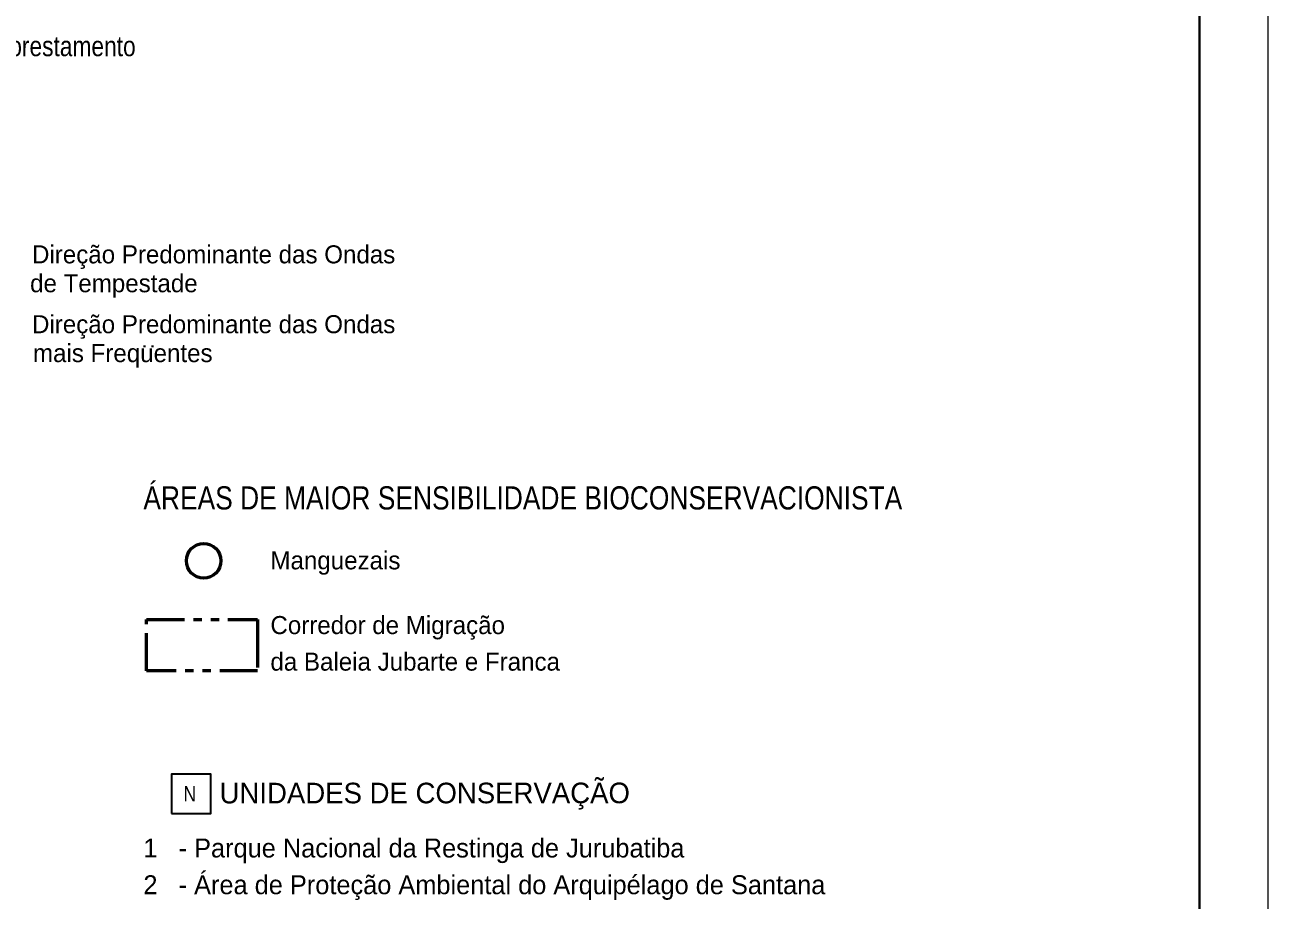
# Model space of a CAD drawing. Extents: x -6.3 to 58.7, y 19.8 to 60.6.
# Drawn here: x 43.55 to 58.68, y 39.84 to 50.49 of the extents above; entities that cross this region are included whole.
import ezdxf
from ezdxf.enums import TextEntityAlignment as Align

# ---------------------------------------------------------------- set-up
doc = ezdxf.new("R2010")
doc.units = 0
doc.header["$LTSCALE"] = 0.092
doc.linetypes.add('DASH_DOUBLE_DOT', pattern=[9.2, 5, -1.2, 0.3, -1.2, 0.3, -1.2])
for name, color, linetype, lineweight in [('58', 7, 'Continuous', 13), ('60', 7, 'Continuous', 40), ('63', 7, 'Continuous', 13)]:
    doc.layers.add(name, color=color, linetype=linetype, lineweight=lineweight)

msp = doc.modelspace()

# ---------------------------------------------------------------- linework, layer by layer
at = {"layer": '58', "lineweight": 35}
for p, q in [((44.99406, 46.5831), (45.01861, 46.5831)), ((45.09224, 46.5831), (45.11679, 46.5831))]:
    msp.add_line(p, q, dxfattribs=at)
at = {"layer": '58', "linetype": 'DASH_DOUBLE_DOT', "lineweight": 53}
msp.add_lwpolyline([(46.38098, 42.63216), (45.03115, 42.63216), (45.03115, 43.22757), (45.03115, 43.25974), (46.02014, 43.25974), (46.38098, 43.25974), (46.38098, 43.13634)], close=True, dxfattribs=at)
at = {"layer": '58', "lineweight": 35}
msp.add_lwpolyline([(45.33382, 40.89857), (45.81228, 40.89857), (45.81228, 41.377), (45.33382, 41.377)], close=True, dxfattribs=at)
at = {"layer": '58', "lineweight": 53}
msp.add_circle((45.72543, 43.97308), 0.21053, dxfattribs=at)
at = {"layer": '60'}
msp.add_lwpolyline([(-3.73781, 29.96257), (-3.73781, 20.65308), (57.84015, 20.65308), (57.84016, 59.74412), (-3.73781, 59.74412), (-3.73781, 40.1986), (-3.73781, 40.1986)], dxfattribs=at)
at = {"layer": '63'}
msp.add_lwpolyline([(-6.28685, 19.8174), (58.67584, 19.8174), (58.67584, 60.5798), (-6.28685, 60.5798)], close=True, dxfattribs=at)

# ---------------------------------------------------------------- texts
at = {"layer": '58', "width": 0.85}
for s, height, p in [('Reflorestamento', 0.2434, (42.86828, 50.1124)), ('ÁREAS DE MAIOR SENSIBILIDADE BIOCONSERVACIONISTA', 0.2822, (44.99192, 44.59709))]:
    msp.add_text(s, height=height, dxfattribs=at).set_placement(p)
at = {"layer": '58'}
for s, height, p in [('Direção Predominante das Ondas', 0.2194, (43.63705, 47.59167)), ('de Tempestade', 0.2194, (43.6137, 47.24008)), ('Direção Predominante das Ondas', 0.2194, (43.63705, 46.74191)), ('mais Frequentes', 0.2194, (43.64876, 46.39033)), ('Manguezais', 0.2194, (46.53736, 43.8686)), ('Corredor de Migração', 0.2194, (46.53736, 43.08115)), ('da Baleia Jubarte e Franca', 0.2194, (46.53736, 42.63628)), ('1   - Parque Nacional da Restinga de Jurubatiba', 0.2306, (44.99192, 40.36336)), ('2   - Área de Proteção Ambiental do Arquipélago de Santana', 0.2306, (44.99192, 39.91614))]:
    msp.add_text(s, height=height, dxfattribs=at).set_placement(p)
msp.add_text('UNIDADES DE CONSERVAÇÃO', height=0.2507, rotation=0.028, dxfattribs=at).set_placement((48.41509, 41.02222), align=Align.CENTER)
at = {"layer": '58', "width": 0.85}
msp.add_text('N', height=0.1882, dxfattribs=at).set_placement((45.55612, 41.04478), align=Align.CENTER)

doc.saveas('drawing.dxf')
